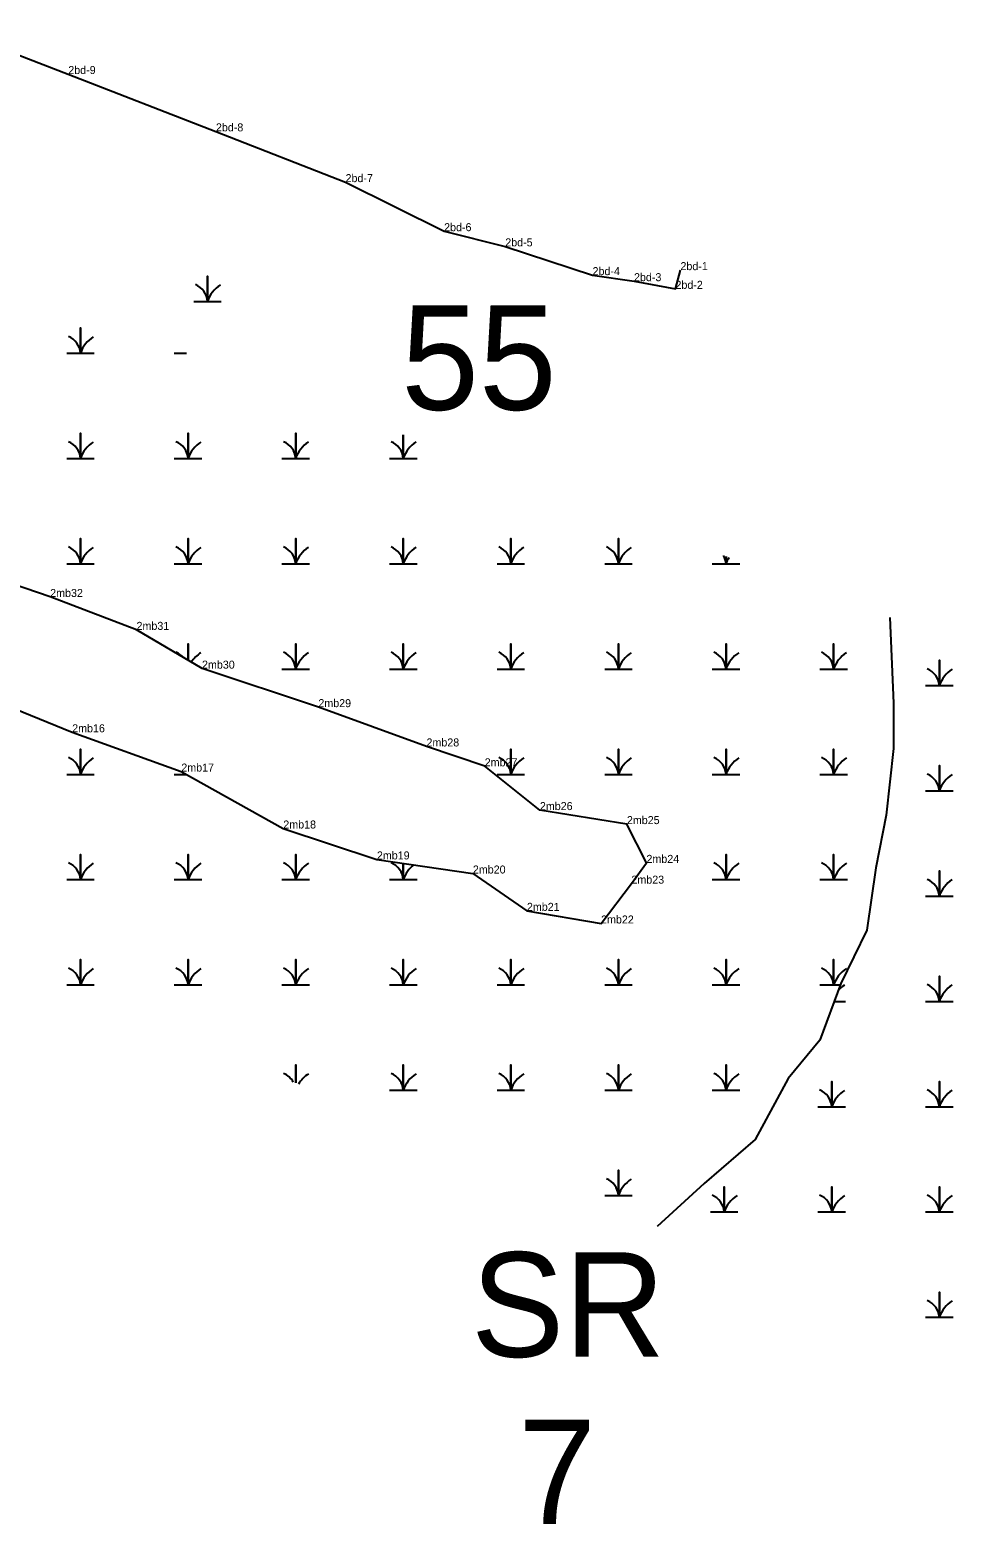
# Model space of a CAD drawing. Extents: x 2072529 to 2268796, y 436423 to 470406.
# Drawn here: x 2105472 to 2106049, y 454077 to 455011 of the extents above; entities that cross this region are included whole.
import ezdxf

# ---------------------------------------------------------------- set-up
doc = ezdxf.new("R2010")
doc.units = 0
for name, color, linetype in [('Default', 7, 'Continuous'), ('Exist Environmental Wetland Boundary', 7, 'Continuous'), ('Exist Environmental Wetland Boundary Cogo Comment', 7, 'Continuous'), ('Exist Hydro Jurisdictional Stream or Body of Water NEU Mitigable', 7, 'Continuous'), ('Exist Hydro Swamp or Marsh', 7, 'Continuous'), ('Old_Level_20', 7, 'Continuous')]:
    doc.layers.add(name, color=color, linetype=linetype)

msp = doc.modelspace()

# ---------------------------------------------------------------- linework, layer by layer
at = {"layer": 'Exist Environmental Wetland Boundary'}
for points in [[(2105423.92, 455010.69), (2105495.92, 454983.09), (2105588.21, 454947.27), (2105669.22, 454915.55), (2105730.84, 454884.87), (2105769.05, 454875.39), (2105823.62, 454857.42), (2105849.53, 454853.64), (2105875.44, 454848.85), (2105878.55, 454860.54)], [(2105441.4, 454594.88), (2105498.36, 454571.72), (2105566.56, 454547.18), (2105630.31, 454511.59), (2105688.82, 454492.27), (2105748.81, 454483.46), (2105782.59, 454460.13), (2105828.94, 454452.23), (2105847.92, 454477.12), (2105857.32, 454490.1), (2105845.09, 454514.34), (2105790.7, 454523.11), (2105756.21, 454550.47), (2105719.82, 454562.88), (2105652.23, 454587.43), (2105579.5, 454611.49), (2105538.58, 454635.73), (2105484.6, 454656.29), (2105412.52, 454680.85)]]:
    msp.add_lwpolyline(points, dxfattribs=at)
at = {"layer": 'Exist Hydro Jurisdictional Stream or Body of Water NEU Mitigable'}
msp.add_lwpolyline([(2106009.39, 454643.4), (2106011.62, 454590.02), (2106011.62, 454561.52), (2106007.24, 454519.87), (2106000.66, 454486.98), (2105995.03, 454448.1), (2105978.75, 454414.63), (2105965.61, 454379.4), (2105945.89, 454355.44), (2105925.28, 454317.23), (2105893.31, 454289.67), (2105863.9, 454262.91)], dxfattribs=at)
at = {"layer": 'Exist Hydro Swamp or Marsh'}
msp.add_line((2105582.94, 454848.14), (2105582.94, 454848.14), dxfattribs=at)
for points in [[(2105574.34, 454841.01), (2105582.94, 454841.01), (2105582.94, 454856.79), (2105582.94, 454841.01), (2105591.54, 454841.01)], [(2105494.95, 454808.64), (2105503.55, 454808.64), (2105503.55, 454824.42), (2105503.55, 454808.64), (2105512.15, 454808.64)], [(2105562.2, 454808.64), (2105569.79, 454808.64)], [(2105494.95, 454742.84), (2105503.55, 454742.84), (2105503.55, 454758.62), (2105503.55, 454742.84), (2105512.15, 454742.84)], [(2105562.2, 454742.84), (2105570.8, 454742.84), (2105570.8, 454758.62), (2105570.8, 454742.84), (2105579.4, 454742.84)], [(2105629.45, 454742.84), (2105638.05, 454742.84), (2105638.05, 454758.62), (2105638.05, 454742.84), (2105646.65, 454742.84)], [(2105696.7, 454742.84), (2105705.3, 454742.84), (2105705.3, 454757.61)], [(2105705.3, 454757.61), (2105705.3, 454742.84), (2105713.9, 454742.84)], [(2105494.95, 454677.04), (2105503.55, 454677.04), (2105503.55, 454692.82), (2105503.55, 454677.04), (2105512.15, 454677.04)], [(2105562.2, 454677.04), (2105570.8, 454677.04), (2105570.8, 454692.82), (2105570.8, 454677.04), (2105579.4, 454677.04)], [(2105629.45, 454677.04), (2105638.05, 454677.04), (2105638.05, 454692.82), (2105638.05, 454677.04), (2105646.65, 454677.04)], [(2105696.7, 454677.04), (2105705.3, 454677.04), (2105705.3, 454692.82), (2105705.3, 454677.04), (2105713.9, 454677.04)], [(2105763.95, 454677.04), (2105772.55, 454677.04), (2105772.55, 454692.82), (2105772.55, 454677.04), (2105781.15, 454677.04)], [(2105831.2, 454677.04), (2105839.8, 454677.04), (2105839.8, 454692.82), (2105839.8, 454677.04), (2105848.4, 454677.04)], [(2105898.45, 454677.04), (2105907.05, 454677.04), (2105907.05, 454681.62)], [(2105907.05, 454681.62), (2105907.05, 454677.04), (2105915.65, 454677.04)], [(2105570.8, 454616.64), (2105570.8, 454627.02), (2105570.8, 454616.64)], [(2105629.45, 454611.24), (2105638.05, 454611.24), (2105638.05, 454627.02), (2105638.05, 454611.24), (2105646.65, 454611.24)], [(2105696.7, 454611.24), (2105705.3, 454611.24), (2105705.3, 454627.02), (2105705.3, 454611.24), (2105713.9, 454611.24)], [(2105763.95, 454611.24), (2105772.55, 454611.24), (2105772.55, 454627.02), (2105772.55, 454611.24), (2105781.15, 454611.24)], [(2105831.2, 454611.24), (2105839.8, 454611.24), (2105839.8, 454627.02), (2105839.8, 454611.24), (2105848.4, 454611.24)], [(2105898.45, 454611.24), (2105907.05, 454611.24), (2105907.05, 454627.02), (2105907.05, 454611.24), (2105915.65, 454611.24)], [(2105965.7, 454611.24), (2105974.3, 454611.24), (2105974.3, 454627.02), (2105974.3, 454611.24), (2105982.9, 454611.24)], [(2106031.78, 454600.93), (2106040.39, 454600.93), (2106040.39, 454616.71), (2106040.39, 454600.93), (2106048.99, 454600.93)], [(2105494.95, 454545.44), (2105503.55, 454545.44), (2105503.55, 454561.22), (2105503.55, 454545.44), (2105512.15, 454545.44)], [(2105763.95, 454545.44), (2105772.55, 454545.44), (2105772.55, 454561.22), (2105772.55, 454545.44), (2105781.15, 454545.44)], [(2105831.2, 454545.44), (2105839.8, 454545.44), (2105839.8, 454561.22), (2105839.8, 454545.44), (2105848.4, 454545.44)], [(2105898.45, 454545.44), (2105907.05, 454545.44), (2105907.05, 454561.22), (2105907.05, 454545.44), (2105915.65, 454545.44)], [(2105965.7, 454545.44), (2105974.3, 454545.44), (2105974.3, 454561.22), (2105974.3, 454545.44), (2105982.9, 454545.44)], [(2106031.78, 454535.13), (2106040.39, 454535.13), (2106040.39, 454550.91), (2106040.39, 454535.13), (2106048.99, 454535.13)], [(2105562.2, 454545.44), (2105569.67, 454545.44)], [(2105494.95, 454479.64), (2105503.55, 454479.64), (2105503.55, 454495.42), (2105503.55, 454479.64), (2105512.15, 454479.64)], [(2105562.2, 454479.64), (2105570.8, 454479.64), (2105570.8, 454495.42), (2105570.8, 454479.64), (2105579.4, 454479.64)], [(2105629.45, 454479.64), (2105638.05, 454479.64), (2105638.05, 454495.42), (2105638.05, 454479.64), (2105646.65, 454479.64)], [(2105898.45, 454479.64), (2105907.05, 454479.64), (2105907.05, 454495.42), (2105907.05, 454479.64), (2105915.65, 454479.64)], [(2105965.7, 454479.64), (2105974.3, 454479.64), (2105974.3, 454495.42), (2105974.3, 454479.64), (2105982.9, 454479.64)], [(2105696.7, 454479.64), (2105705.3, 454479.64), (2105705.3, 454489.85)], [(2105705.3, 454489.85), (2105705.3, 454479.64), (2105713.9, 454479.64)], [(2106031.78, 454469.33), (2106040.39, 454469.33), (2106040.39, 454485.11), (2106040.39, 454469.33), (2106048.99, 454469.33)], [(2105494.95, 454413.84), (2105503.55, 454413.84), (2105503.55, 454429.62), (2105503.55, 454413.84), (2105512.15, 454413.84)], [(2105562.2, 454413.84), (2105570.8, 454413.84), (2105570.8, 454429.62), (2105570.8, 454413.84), (2105579.4, 454413.84)], [(2105629.45, 454413.84), (2105638.05, 454413.84), (2105638.05, 454429.62), (2105638.05, 454413.84), (2105646.65, 454413.84)], [(2105696.7, 454413.84), (2105705.3, 454413.84), (2105705.3, 454429.62), (2105705.3, 454413.84), (2105713.9, 454413.84)], [(2105763.95, 454413.84), (2105772.55, 454413.84), (2105772.55, 454429.62), (2105772.55, 454413.84), (2105781.15, 454413.84)], [(2105831.2, 454413.84), (2105839.8, 454413.84), (2105839.8, 454429.62), (2105839.8, 454413.84), (2105848.4, 454413.84)], [(2105898.45, 454413.84), (2105907.05, 454413.84), (2105907.05, 454429.62), (2105907.05, 454413.84), (2105915.65, 454413.84)], [(2105965.7, 454413.84), (2105974.3, 454413.84), (2105974.3, 454429.62), (2105974.3, 454413.84), (2105978.46, 454413.84)], [(2106031.78, 454403.53), (2106040.39, 454403.53), (2106040.39, 454419.31), (2106040.39, 454403.53), (2106048.99, 454403.53)], [(2105974.61, 454403.53), (2105981.74, 454403.53)], [(2105638.05, 454352.56), (2105638.05, 454363.82), (2105638.05, 454352.56)], [(2105696.7, 454348.04), (2105705.3, 454348.04), (2105705.3, 454363.82), (2105705.3, 454348.04), (2105713.9, 454348.04)], [(2105763.95, 454348.04), (2105772.55, 454348.04), (2105772.55, 454363.82), (2105772.55, 454348.04), (2105781.15, 454348.04)], [(2105831.2, 454348.04), (2105839.8, 454348.04), (2105839.8, 454363.82), (2105839.8, 454348.04), (2105848.4, 454348.04)], [(2105898.45, 454348.04), (2105907.05, 454348.04), (2105907.05, 454363.82), (2105907.05, 454348.04), (2105915.65, 454348.04)], [(2105964.53, 454337.73), (2105973.14, 454337.73), (2105973.14, 454353.51), (2105973.14, 454337.73), (2105981.74, 454337.73)], [(2106031.78, 454337.73), (2106040.39, 454337.73), (2106040.39, 454353.51), (2106040.39, 454337.73), (2106048.99, 454337.73)], [(2105831.2, 454282.24), (2105839.8, 454282.24), (2105839.8, 454298.02), (2105839.8, 454282.24), (2105848.4, 454282.24)], [(2105897.28, 454271.93), (2105905.89, 454271.93), (2105905.89, 454287.71), (2105905.89, 454271.93), (2105914.49, 454271.93)], [(2105964.53, 454271.93), (2105973.14, 454271.93), (2105973.14, 454287.71), (2105973.14, 454271.93), (2105981.74, 454271.93)], [(2106031.78, 454271.93), (2106040.39, 454271.93), (2106040.39, 454287.71), (2106040.39, 454271.93), (2106048.99, 454271.93)], [(2106031.78, 454206.13), (2106040.39, 454206.13), (2106040.39, 454221.91), (2106040.39, 454206.13), (2106048.99, 454206.13)]]:
    msp.add_lwpolyline(points, dxfattribs=at)
for centre, radius, start, end in [((2105570.67, 454840.12), 12.3, 4.14034, 67.53497), ((2105601.18, 454834.95), 19.22, 122.12745, 161.62219), ((2105491.28, 454807.76), 12.3, 4.14034, 67.53497), ((2105521.79, 454802.58), 19.22, 122.12745, 161.62219), ((2105491.28, 454741.96), 12.3, 4.14034, 67.53497), ((2105558.53, 454741.96), 12.3, 4.14034, 67.53497), ((2105625.78, 454741.96), 12.3, 4.14034, 67.53497), ((2105693.03, 454741.96), 12.3, 4.14034, 67.53497), ((2105521.79, 454736.78), 19.22, 122.12745, 161.62219), ((2105589.04, 454736.78), 19.22, 122.12745, 161.62219), ((2105656.29, 454736.78), 19.22, 122.12745, 161.62219), ((2105723.54, 454736.78), 19.22, 122.12745, 161.62219), ((2105491.28, 454676.16), 12.3, 4.14034, 67.53497), ((2105521.79, 454670.98), 19.22, 122.12745, 161.62219), ((2105558.53, 454676.16), 12.3, 4.14034, 67.53497), ((2105589.04, 454670.98), 19.22, 122.12745, 161.62219), ((2105625.78, 454676.16), 12.3, 4.14034, 67.53497), ((2105656.29, 454670.98), 19.22, 122.12745, 161.62219), ((2105693.03, 454676.16), 12.3, 4.14034, 67.53497), ((2105723.54, 454670.98), 19.22, 122.12745, 161.62219), ((2105760.28, 454676.16), 12.3, 4.14034, 67.53497), ((2105790.79, 454670.98), 19.22, 122.12745, 161.62219), ((2105827.53, 454676.16), 12.3, 4.14034, 67.53497), ((2105858.04, 454670.98), 19.22, 122.12745, 161.62219), ((2105894.78, 454676.16), 12.3, 4.14034, 29.50947), ((2105925.29, 454670.98), 19.22, 148.78323, 161.62219), ((2105558.53, 454610.36), 12.3, 40.84562, 67.53497), ((2105589.04, 454605.18), 19.22, 122.12745, 147.67873), ((2105625.78, 454610.36), 12.3, 4.14034, 67.53497), ((2105656.29, 454605.18), 19.22, 122.12745, 161.62219), ((2105693.03, 454610.36), 12.3, 4.14034, 67.53497), ((2105723.54, 454605.18), 19.22, 122.12745, 161.62219), ((2105760.28, 454610.36), 12.3, 4.14034, 67.53497), ((2105790.79, 454605.18), 19.22, 122.12745, 161.62219), ((2105827.53, 454610.36), 12.3, 4.14034, 67.53497), ((2105858.04, 454605.18), 19.22, 122.12745, 161.62219), ((2105894.78, 454610.36), 12.3, 4.14034, 67.53497), ((2105925.29, 454605.18), 19.22, 122.12745, 161.62219), ((2105962.03, 454610.36), 12.3, 4.14034, 67.53497), ((2105992.54, 454605.18), 19.22, 122.12745, 161.62219), ((2106028.12, 454600.04), 12.3, 4.14034, 67.53497), ((2106058.63, 454594.86), 19.22, 122.12745, 161.62219), ((2105491.28, 454544.56), 12.3, 4.14034, 67.53497), ((2105521.79, 454539.38), 19.22, 122.12745, 161.62219), ((2105760.28, 454544.56), 12.3, 4.14034, 67.53497), ((2105790.79, 454539.38), 19.22, 122.12745, 161.62219), ((2105827.53, 454544.56), 12.3, 4.14034, 67.53497), ((2105858.04, 454539.38), 19.22, 122.12745, 161.62219), ((2105894.78, 454544.56), 12.3, 4.14034, 67.53497), ((2105925.29, 454539.38), 19.22, 122.12745, 161.62219), ((2105962.03, 454544.56), 12.3, 4.14034, 67.53497), ((2105992.54, 454539.38), 19.22, 122.12745, 161.62219), ((2106028.12, 454534.24), 12.3, 4.14034, 67.53497), ((2106058.63, 454529.06), 19.22, 122.12745, 161.62219), ((2105491.28, 454478.76), 12.3, 4.14034, 67.53497), ((2105521.79, 454473.58), 19.22, 122.12745, 161.62219), ((2105558.53, 454478.76), 12.3, 4.14034, 67.53497), ((2105589.04, 454473.58), 19.22, 122.12745, 161.62219), ((2105625.78, 454478.76), 12.3, 4.14034, 67.53497), ((2105656.29, 454473.58), 19.22, 122.12745, 161.62219), ((2105693.03, 454478.76), 12.3, 4.14034, 67.53497), ((2105723.54, 454473.58), 19.22, 127.26595, 161.62219), ((2105894.78, 454478.76), 12.3, 4.14034, 67.53497), ((2105925.29, 454473.58), 19.22, 122.12745, 161.62219), ((2105962.03, 454478.76), 12.3, 4.14034, 67.53497), ((2105992.54, 454473.58), 19.22, 122.12745, 161.62219), ((2106028.12, 454468.44), 12.3, 4.14034, 67.53497), ((2106058.63, 454463.26), 19.22, 122.12745, 161.62219), ((2105491.28, 454412.96), 12.3, 4.14034, 67.53497), ((2105521.79, 454407.78), 19.22, 122.12745, 161.62219), ((2105558.53, 454412.96), 12.3, 4.14034, 67.53497), ((2105589.04, 454407.78), 19.22, 122.12745, 161.62219), ((2105625.78, 454412.96), 12.3, 4.14034, 67.53497), ((2105656.29, 454407.78), 19.22, 122.12745, 161.62219), ((2105693.03, 454412.96), 12.3, 4.14034, 67.53497), ((2105723.54, 454407.78), 19.22, 122.12745, 161.62219), ((2105760.28, 454412.96), 12.3, 4.14034, 67.53497), ((2105790.79, 454407.78), 19.22, 122.12745, 161.62219), ((2105827.53, 454412.96), 12.3, 4.14034, 67.53497), ((2105858.04, 454407.78), 19.22, 122.12745, 161.62219), ((2105894.78, 454412.96), 12.3, 4.14034, 67.53497), ((2105925.29, 454407.78), 19.22, 122.12745, 161.62219), ((2105962.03, 454412.96), 12.3, 4.14034, 67.53497), ((2105992.54, 454407.78), 19.22, 122.12745, 161.62219), ((2105991.38, 454397.46), 19.22, 122.12745, 137.58861), ((2106028.12, 454402.64), 12.3, 4.14034, 67.53497), ((2106058.63, 454397.46), 19.22, 122.12745, 161.62219), ((2105625.78, 454347.16), 12.3, 29.0926, 67.53497), ((2105656.29, 454341.98), 19.22, 122.12745, 148.95552), ((2105693.03, 454347.16), 12.3, 4.14034, 67.53497), ((2105723.54, 454341.98), 19.22, 122.12745, 161.62219), ((2105760.28, 454347.16), 12.3, 4.14034, 67.53497), ((2105790.79, 454341.98), 19.22, 122.12745, 161.62219), ((2105827.53, 454347.16), 12.3, 4.14034, 67.53497), ((2105858.04, 454341.98), 19.22, 122.12745, 161.62219), ((2105894.78, 454347.16), 12.3, 4.14034, 67.53497), ((2105925.29, 454341.98), 19.22, 122.12745, 161.62219), ((2105960.87, 454336.84), 12.3, 4.14034, 67.53497), ((2105991.38, 454331.66), 19.22, 122.12745, 161.62219), ((2106028.12, 454336.84), 12.3, 4.14034, 67.53497), ((2106058.63, 454331.66), 19.22, 122.12745, 161.62219), ((2105827.53, 454281.36), 12.3, 4.14034, 67.53497), ((2105858.04, 454276.18), 19.22, 122.12745, 161.62219), ((2105893.62, 454271.04), 12.3, 4.14034, 67.53497), ((2105924.13, 454265.86), 19.22, 122.12745, 161.62219), ((2105960.87, 454271.04), 12.3, 4.14034, 67.53497), ((2105991.38, 454265.86), 19.22, 122.12745, 161.62219), ((2106028.12, 454271.04), 12.3, 4.14034, 67.53497), ((2106058.63, 454265.86), 19.22, 122.12745, 161.62219), ((2106028.12, 454205.24), 12.3, 4.14034, 67.53497), ((2106058.63, 454200.06), 19.22, 122.12745, 161.62219)]:
    msp.add_arc(centre, radius, start, end, dxfattribs=at)
at = {"layer": 'Old_Level_20'}
for p, q in [((2105495.92, 454983.09), (2105495.92, 454983.09)), ((2105588.21, 454947.27), (2105588.21, 454947.27)), ((2105669.22, 454915.55), (2105669.22, 454915.55)), ((2105730.84, 454884.87), (2105730.84, 454884.87)), ((2105769.05, 454875.39), (2105769.05, 454875.39)), ((2105823.62, 454857.42), (2105823.62, 454857.42)), ((2105878.55, 454860.54), (2105878.55, 454860.54)), ((2105849.53, 454853.64), (2105849.53, 454853.64)), ((2105875.44, 454848.85), (2105875.44, 454848.85)), ((2105484.6, 454656.29), (2105484.6, 454656.29)), ((2105538.58, 454635.73), (2105538.58, 454635.73)), ((2105579.5, 454611.49), (2105579.5, 454611.49)), ((2105652.23, 454587.43), (2105652.23, 454587.43)), ((2105498.36, 454571.72), (2105498.36, 454571.72)), ((2105719.82, 454562.88), (2105719.82, 454562.88)), ((2105756.21, 454550.47), (2105756.21, 454550.47)), ((2105566.56, 454547.18), (2105566.56, 454547.18)), ((2105790.7, 454523.11), (2105790.7, 454523.11)), ((2105630.31, 454511.59), (2105630.31, 454511.59)), ((2105845.09, 454514.34), (2105845.09, 454514.34)), ((2105688.82, 454492.27), (2105688.82, 454492.27)), ((2105748.81, 454483.46), (2105748.81, 454483.46)), ((2105857.32, 454490.1), (2105857.32, 454490.1)), ((2105847.92, 454477.12), (2105847.92, 454477.12)), ((2105782.59, 454460.13), (2105782.59, 454460.13)), ((2105828.94, 454452.23), (2105828.94, 454452.23))]:
    msp.add_line(p, q, dxfattribs=at)

# ---------------------------------------------------------------- texts
at = {"layer": 'Default'}
for s, p in [('55', (2105704, 454773.25)), ('SR', (2105747.65, 454181.41)), ('7', (2105777.21, 454076.86))]:
    msp.add_text(s, height=65.34, dxfattribs=at).set_placement(p)
at = {"layer": 'Exist Environmental Wetland Boundary Cogo Comment'}
for s, p in [('2bd-9', (2105495.92, 454983.09)), ('2bd-8', (2105588.21, 454947.27)), ('2bd-7', (2105669.22, 454915.55)), ('2bd-6', (2105730.84, 454884.87)), ('2bd-5', (2105769.05, 454875.39)), ('2bd-1', (2105878.55, 454860.54)), ('2bd-4', (2105823.62, 454857.42)), ('2bd-3', (2105849.53, 454853.64)), ('2bd-2', (2105875.44, 454848.85)), ('2mb32', (2105484.6, 454656.29)), ('2mb31', (2105538.58, 454635.73)), ('2mb30', (2105579.5, 454611.49)), ('2mb29', (2105652.23, 454587.43)), ('2mb16', (2105498.36, 454571.72)), ('2mb28', (2105719.82, 454562.88)), ('2mb17', (2105566.56, 454547.18)), ('2mb27', (2105756.21, 454550.47)), ('2mb26', (2105790.7, 454523.11)), ('2mb18', (2105630.31, 454511.59)), ('2mb25', (2105845.09, 454514.34)), ('2mb19', (2105688.82, 454492.27)), ('2mb24', (2105857.32, 454490.1)), ('2mb20', (2105748.81, 454483.46)), ('2mb23', (2105847.92, 454477.12)), ('2mb21', (2105782.59, 454460.13)), ('2mb22', (2105828.94, 454452.23))]:
    msp.add_text(s, height=5, dxfattribs=at).set_placement(p)

doc.saveas('drawing.dxf')
